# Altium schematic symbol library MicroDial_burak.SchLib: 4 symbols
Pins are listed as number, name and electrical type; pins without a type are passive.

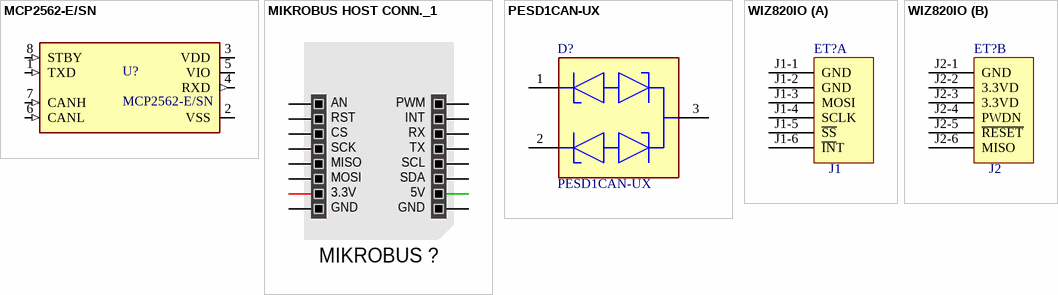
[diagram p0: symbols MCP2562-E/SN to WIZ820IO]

## MCP2562-E/SN
designator U?
MCP2562-E/SN Bus CAN, Émetteur-récepteur, CAN, LIN, 1, 1, 4.5 V, 5.5 V, SOIC; Code Commande: F236-2839
footprint SOIC127P600X175-8N
pins: 1 TXD (in), 2 VSS (power), 3 VDD (power), 4 RXD (out), 5 VIO (power), 6 CANL (in), 7 CANH (in), 8 STBY (in)

## MIKROBUS HOST CONN._1
designator MIKROBUS ?, comment MIKROBUS HOST CONN.  (value not drawn)
mikroBUS Host Socket
footprint MIKROBUS HOST CONN.
pins: 1 AN, 2 RST, 3 CS, 4 SCK, 5 MISO, 6 MOSI, 7 3.3V, 8 GND, 9 GND, 10 5V, 11 SDA, 12 SCL, 13 TX, 14 RX, 15 INT, 16 PWM

## PESD1CAN-UX
designator D?
Circuit de protection ESD, 50 V, SOT-323, 3 Broche(s), 150 W, PESD1 Series; Code Commande: F2357118
footprint FP-SOT323-IPC_C
footprint FP-SOT323-IPC_B
footprint FP-SOT323-IPC_A
footprint FP-SOT323-MFG
pins: 1 cathode 1, 2 cathode 2, 3 common cathode

## WIZ820IO
designator ET?, comment Module ETHERNET WIZNET WIZ820IO  (value not drawn)
IC MODULE W5200+MAG JACK Ethernet Contrôleur 10/100 Base-T/TX PHY SPI Interface Module WIZ820IO; Code Commande: Mouser 950-WIZ820IO + Digi-key  1278-1015-ND
footprint WIZ820io-V1.0 (WIZ820io module Ethernet V1.0)
part A pins: J1-1 GND, J1-2 GND, J1-3 MOSI, J1-4 SCLK, J1-5 ~{SS} "/SS", J1-6 ~{IN}T "/INT"
part B pins: J2-1 GND, J2-2 3.3VD, J2-3 3.3VD, J2-4 PWDN, J2-5 ~{RESET} "/RESET", J2-6 MISO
